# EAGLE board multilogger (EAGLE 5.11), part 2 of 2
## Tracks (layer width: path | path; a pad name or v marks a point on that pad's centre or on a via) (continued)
N$23 (continued)
  Top 0.254: R38.1 51.38,156.84 52.42,156.84 52.99,156.2 53.8,156.2 54.63,156.23 IC1.10
N$24  (via drill 0.3)
  Top 0.254: v61.94,32.68 61.94,31.26 R16.2
  Bottom 0.254: v61.94,32.68 61.4,32.72 60.99,32.72 59.91,34.31 59.91,34.72 X1.8
N$25
  Top 0.254: R18.2 4.64,67.02 4.64,62.76 5.66,61.74 IN3_PLUS_CON.MP | R18.2
N$26
  Top 0.254: R19.2 10.74,56.46 10.74,56.25 10.13,55.65 5.86,55.65 5.86,56.46 IN3_MINUS_CON.MP | R19.2
N$27
  Top 0.254: IC1.4 63.91,152.5 C20.1
N$28
  Top 0.254: IC1.5 63.91,153.76 C20.2
N$29
  Top 0.254: R20.2 10.74,50.36 5.86,50.36 5.86,51.38 IN4_PLUS_CON.MP
N$30
  Top 0.254: R21.2 10.74,45.28 9.52,45.28 8.5,46.3 5.86,46.3 IN4_MINUS_CON.MP
N$31
  Top 0.254: C21.1 58.9,144.24 58.9,148.71 60.12,149.93 60.93,149.93 IC1.2
N$32
  Top 0.254: IC1.6 62.17,155.03 63.57,156.43 63.57,157.23 C22.1
N$33
  Top 0.254: R24.2 50.36,162.32 53,162.32 53,163.14 53.14,163.28 55.17,163.28 55.24,161.92 56.05,161.11 57.58,159.78 57.68,158.67 57.68,153.18 55.85,151.35 54.83,151.35 IC1.14
N$34
  Top 0.254: R25.2 54.22,162.32 54.88,160.65 55.65,160.09 56.76,158.46 56.76,153.99 55.85,152.57 54.83,152.57 IC1.13
N$35
  Top 0.254: R24.1 50.36,164.36 50.36,168.22 RS232-TX-CON.MP
N$36
  Top 0.254: R25.1 54.02,164.36 54.02,168.22 RS232-RX-CON.MP
N$37
  Top 0.254: R36.1 54.63,154.4 54.63,155.01 IC1.11
N$38
  Top 0.254: X2.2 12.79,24.54 13.79,23.54 13.8,23.54 R28.2
N$39
  Top 0.254: R37.1 51.38,151.96 52.39,151.96 52.39,152.16 53.82,153.59 54.63,153.59 IC1.12
N$40  (via drill 0.3)
  Top 0.254: v53.27,157.25 54.63,157.25 54.63,157.45 IC1.9 | R39.1 v52.8,142.61
  Bottom 0.254: v52.8,142.61 52.8,156.79 53,157.04 v53.27,157.25
N$41
  Top 0.254: X2.3 12.77,23.74 13.38,23.13 13.38,20.15 R29.2
N$43
  Top 0.254: C25.1 17.55,25.5 IC2.3 20.29,25.37 20.29,24.35 IC2.4 20.29,24.15 20.29,23.13 IC2.5
N$44
  Top 0.254: R40.2 61.74,162.32 62.15,161.92 62.15,158.34 62.35,157.85 62.35,156.97 61.54,156.15 61.13,156.43 IC1.7
N$45
  Top 0.254: R41.2 57.88,162.32 60.93,159.28 60.93,157.65 IC1.8
N$46  (via drill 0.3)
  Top 0.254: v59.62,65.17 59.3,65.6 58.08,65.6 IC7.33 | v48.33,55.03 47.31,54.02 47.31,52.6 BUTTON4.MP
  Bottom 0.254: v59.62,65.17 58.29,63.98 58.29,61.94 58.49,61.94 59.1,61.33 59.1,59.51 51.17,59.51 50.16,58.49 50.16,56.86 v48.33,55.03
N$47  (via drill 0.3)
  Top 0.254: v57.84,61.18 57.55,61.26 56.86,61.77 55.9,62.91 55.9,64.38 56.51,64.99 57.88,64.99 IC7.32 | v43.66,60.73 43.45,60.52 43.45,58.9 43.25,58.69 43.25,57.88 42.49,56.84 42.49,55.8 38.58,54.38 38.58,50.16 35.58,45.38 24.81,45.38 24.55,47.52 v22.52,49.55 | v16.02,49.14 14.6,49.14 14.39,48.94 4.03,48.94 4.03,72.92 10.94,77.03 10.94,78.81 BUTTON3.MP
  Bottom 0.254: v57.84,61.18 57.47,60.73 v43.66,60.73 | v22.52,49.55 22.12,49.14 v16.02,49.14
N$48
  Top 0.254: R40.1 61.74,164.36 61.74,168.22 RS232-RTS-CON.MP
N$49
  Top 0.254: R41.1 RS232-CTS-CON.MP
N$50
  Top 0.254: R43.1 78.2,146.47 77.79,146.88 77.79,148.3 75.36,150.74 75.15,150.74 75.15,150.54 IC8.4
N$51  (via drill 0.3)
  Top 0.254: v49.14,69.26 49.14,67.71 49.95,67.02 50.72,63.98 52.32,61.74 52.32,60.32 IC7.17 | v39.6,69.54 39.67,69.37 39.36,69.2 36.82,69.2 36.63,69.73 36.42,70.52 36.38,72.29 34.42,75.2 31.41,75.39 31.4,77.44 30.7,84.8 BUTTON2.MP
  Bottom 0.254: v49.14,69.26 48.74,69.47 v39.6,69.54
N$52  (via drill 0.3)
  Top 0.254: v42.64,58.08 42.64,58.9 43.05,59.3 43.05,61.33 48.33,61.33 49.38,62.01 49.89,62.21 50.97,62.27 51.78,61.33 51.78,60.32 IC7.16 | v33.9,54.02 33.09,53.21 33.09,52.6 BUTTON1.MP
  Bottom 0.254: v42.64,58.08 42.44,58.29 38.17,58.29 37.56,57.68 37.56,56.5 36.82,56.5 v33.9,54.02
N$53
  Top 0.254: IC2.6 17.55,21.68 R28.1
N$54
  Top 0.254: IC2.7 18.82,20.41 R29.1
N$55
  Top 0.254: R42.1 70.68,146.47 71.09,146.88 71.09,150.34 IC8.1
N$56
  Top 0.254: R44.1 74.34,146.47 74.34,149.93 73.93,150.34 IC8.3
N$57
  Top 0.254: IC2.11 32.8,21.68 R30.2
N$58
  Top 0.254: R45.2 51.38,93.24 51.38,97.1 OLED.5
N$59
  Top 0.254: IC2.10 30.89,20.41 R31.2
N$60  (via drill 0.3)
  Top 0.254: 61.74,37.76 63.16,37.76 63.16,37.15 63.98,36.34 63.98,35.12 R17.2 | v61.74,36.75 61.74,37.76 | 61.74,37.76 R53.1
  Bottom 0.254: v61.74,36.75 61.74,34.92 X1.7
N$61
  Top 0.254: R47.2 44.06,93.24 44.27,93.44 44.27,94.86 46.3,96.89 46.3,97.1 OLED.9
N$62
  Top 0.254: R46.2 55.24,93.24 55.03,93.44 55.03,95.47 54.02,96.49 54.02,97.1 OLED.3
N$63  (via drill 0.3)
  Top 0.254: v66.62,36.75 66.62,37.76 R52.1
  Bottom 0.254: v66.62,36.75 66.62,34.92 X1.5
N$64  (via drill 0.3)
  Top 0.254: v60.12,32.48 60.12,32.68 58.08,34.72 58.08,36.34 56.66,37.76 R51.1
  Bottom 0.254: v60.12,32.48 60.52,32.07 72.71,32.07 74.14,33.5 74.14,34.72 X1.2
N$65  (via drill 0.3)
  Top 0.254: v65.6,38.78 65.6,37.97 64.38,37.97 R50.1
  Bottom 0.254: v65.6,38.78 66.82,37.56 70.89,37.56 71.09,37.36 73.93,37.36 76.37,34.92 76.57,34.92 X1.1
N$66  (via drill 0.3)
  Top 0.254: v58.69,35.12 59.1,35.53 59.1,37.36 | 59.1,37.36 59.1,37.76 R48.2 59.1,37.36 | 59.1,37.36 57.68,38.84 55.65,38.84 55.44,38.58 55.44,37.97 54.22,37.97 R5.1
  Bottom 0.254: v58.69,35.12 57.88,34.31 X1.DETECT
N$67  (via drill 0.3)
  Top 0.254: 63.37,62.96 v63.37,64.59 | v64.99,65.4 65.13,66.36 65.19,66.62 R49.2 | v71.09,29.23 71.49,29.64 71.49,36.95 70.68,37.76 70.68,44.27 71.7,45.28 71.7,53.61 70.26,55.34 69.28,56.32 v68.67,56.32 | v63.57,61.74 63.37,61.94 63.37,62.96 | 63.37,62.96 R7.1
  Bottom 0.254: v63.37,64.59 64.18,65.4 v64.99,65.4 | v71.09,29.23 64.79,22.93 57.07,22.93 56.66,22.52 X1.WRITE_PROT | v68.67,56.32 v63.57,61.74
N$68
  Top 0.254: IC9.1 66.21,94.25 62.76,94.25 62.76,94.66 R54.1
N$69
  Top 0.254: IC9.2 66.21,93.64 64.99,93.64 62.76,91.41 62.76,91 R55.1
N$70
  Top 0.254: IC10.36 69.06,127.37 68.45,127.98 66.82,127.98 66.21,128.59 61.74,128.59 61.74,139.16 AD9540_CP_OUT.MP
N$71  (via drill 0.3)
  Top 0.254: v65.6,125.14 66.54,125.75 68.02,125.75 68.12,125.67 68.62,125.67 IC10.39
  Bottom 0.254: v65.6,125.14 60.46,130.09 55.99,130.09 54.22,131.73 54.22,135.3 56.46,135.3 AD9540_REFIN.MP
N$73
  Top 0.254: IC7.56 53.76,77.04 52.58,81.12 52.39,81.78 Y2.4 52.16,83.92 51.58,84.5 48.72,84.5 C13.1
N$74
  Top 0.254: IC7.55 54.26,77.02 54.29,80.3 55.24,81.91 Y2.1 | Y2.1 55.66,82.01 | C12.1 56.7,83.55 56.24,83.09 55.24,82.11 Y2.1
N$75
  Top 0.254: IC7.43 66.21,70.54 68.43,76.26 70.68,80.44 70.68,81.33 Y1.2 75.19,81.53 C15.1
N$76
  Top 0.254: IC7.42 68.49,70.04 Y1.1 74.89,72.03 C14.1
N$77  (via drill 0.3)
  Top 0.254: v67.63,125.14 68.45,125.14 IC10.40
  Bottom 0.254: v67.63,125.14 66.61,123.92 !AD9540_REFIN.MP
N$78  (via drill 0.3)
  Top 0.254: v73.32,130.63 73.32,130.14 72.59,129.53 72.59,127.45 IC10.29
  Bottom 0.254: v73.32,130.63 73.32,139.16 AD9540_CLK1.MP
N$79  (via drill 0.3)
  Top 0.254: v73.21,129.22 73.12,129 73.12,127.37 IC10.28
  Bottom 0.254: v73.21,129.22 73.78,130.02 76.98,133.47 76.98,139.16 !AD9540_CLK1.MP
N$80  (via drill 0.3)
  Top 0.254: v66.21,124.53 66.21,124.12 68.45,124.12 IC10.42
  Bottom 0.254: v66.21,124.53 61.94,124.53 58.69,127.78 56.66,127.78 AD9540_CLK2.MP
N$81  (via drill 0.3)
  Top 0.254: v66.82,125.14 67.18,124.53 68.03,124.53 68.17,124.63 68.45,124.68 IC10.41
  Bottom 0.254: v66.82,125.14 60.52,131.44 56.66,131.44 !AD9540_CLK2.MP
N$82
  Top 0.254: IC10.9 73.09,120.49 73.09,119.47 73.13,118.99 73.13,118.79 73.48,117.81 73.73,117.21 74.34,116.61 74.34,108.68 AD9540_IO_RESET.MP
N$83
  Top 0.254: AD9540_RESET.MP 78.2,110.71 74.75,114.17 74.75,116.81 74.34,117.21 73.89,118.39 73.58,119.68 73.58,120.49 IC10.10
N$84  (via drill 0.3)
  Top 0.254: v76.02,120.42 75.36,121.08 IC10.13
  Bottom 0.254: v76.02,120.42 82.06,114.37 82.06,108.68 AD9540_SD0.MP
N$85  (via drill 0.3)
  Top 0.15: v76.98,120.47 75.76,121.69 75.15,121.69 IC10.14
  Bottom 0.15: v76.98,120.47 84.5,112.95 84.5,112.74 AD9540_SDIO.MP
  Bottom 0.254: AD9540_SDIO.MP 84.55,112.74
N$86  (via drill 0.3)
  Top 0.254: v77.36,121.18 75.7,122.17 IC10.15
  Bottom 0.254: v77.36,121.18 81.76,116.53 84.5,116.4 AD9540_SCLK.MP
N$87  (via drill 0.3)
  Top 0.254: v76.66,122.43 75.97,122.7 75.15,122.7 IC10.16
  Bottom 0.254: v76.66,122.43 82.02,121.71 84.5,120.06 !AD9540_CS.MP
N$88  (via drill 0.3)
  Top 0.254: v67.44,121.32 67.63,121.69 68.45,121.69 IC10.47
  Bottom 0.254: v67.44,121.32 65.81,120.06 60.73,120.06 59.1,118.43 59.1,112.54 56.66,112.54 AD9540_DAC_RSET.MP
N$89  (via drill 0.3, 0.3 pad 0.25)
  Top 0.254: IC10.46 68.08,122.23 67.6,122.21 66.71,121.83 v65.82,122.84 | v55.34,118.33 55.34,117.57 AD9540_DRV_RSET.MP
  Bottom 0.254: v65.82,122.84 58.9,122.84 55.21,121.32 55.21,118.46 v55.34,118.33
N$90  (via drill 0.3)
  Top 0.254: v66.77,122.74 68.4,122.67 IC10.45
  Bottom 0.254: v66.77,122.74 66.21,122.09 60.73,122.09 58.69,120.06 56.66,120.06 AD9540_CP_RSET.MP
N$91
  Top 0.254: IC10.23 75.15,126.16 75.6,126.18 76.12,126.55 79.22,129.2 79.22,137.53 84.5,142.82 AD9540_S2.MP
N$92
  Top 0.254: IC10.22 75.94,125.67 79.62,127.72 79.62,134.08 84.5,138.96 84.5,139.16 AD9540_S1.MP
N$93
  Top 0.254: IC10.21 75.15,125.14 76.22,125.14 77.54,125.62 78.4,126.23 80.22,127.42 80.28,130.76 AD9540_S0.MP
N$94
  Top 0.254: IC10.20 76.36,124.68 77.44,125 80.3,126.33 81.5,127.98 84.3,129.89 AD9540_IO_UPDATE.MP
N$95
  Top 0.254: IC10.19 76.57,124.17 78.47,124.92 80.36,125.43 82.26,127.78 84.5,127.78 AD9540_SYNC_IN.MP
N$96  (via drill 0.3)
  Top 0.254: v77.39,123.79 77.39,123.72 75.15,123.72 IC10.18
  Bottom 0.254: v77.39,123.79 AD9540_SYNC_OUT.MP
N$97  (via drill 0.3)
  Top 0.254: v71.49,118.43 71.49,119.25 71.6,119.42 71.6,120.44 IC10.6
  Bottom 0.254: v71.49,118.43 66.82,113.76 66.82,108.68 !AD9540_IOUT.MP
N$98
  Top 0.254: IC10.5 71.09,120.47 71.09,119.65 69.67,118.23 69.67,111.73 70.48,110.92 70.48,108.68 AD9540_IOUT.MP
N$99
  Top 0.254: IC10.32 71.09,127.37 71.09,129.61 69.87,130.83 69.87,136.52 69.26,137.13 69.26,139.16 !AD9540_OUT0.MP
N$100
  Top 0.254: IC10.33 70.61,127.45 70.61,129.28 69.46,130.42 69.46,135.1 65.6,138.96 65.6,139.16 AD9540_OUT0.MP
N$101
  Top 0.254: D9.A 17.24,8.35 9V-BAT-PLUS-CON.MP
N$102
  Bottom 0.254: POWER-PLUS-CON.MP D10.A
N$104
  Top 0.254: IC5.4 60.32,106.44 60.32,103.8 60.12,103.6 C36.2
N$105
  Top 0.254: C30.2 IC3.1 45.18,22.32 38.83,22.32 38.83,13.43 33.75,13.43 D9.C
  Bottom 0.254: D10.C 45.18,22.32 IC3.1
N$106
  Top 0.254: IC3.3 40.1,29.23 38.98,29.23 38.98,32.89 C31.2 39.05,34.51 42.23,34.51 42.64,32.8 C37.2 43.86,32.77 IC6.8
N$107
  Top 0.254: IC11.7 80.03,52.6 82.06,52.6 82.06,52.39 84.09,50.36 84.5,50.36 CODEC_LRCOUT.MP
N$108
  Top 0.254: C38.2 28.99,34.99 IC13.4 29.73,36.14 47.11,36.14 47.92,35.33 47.92,34.51 47.49,34.08 IC6.6
N$109
  Top 0.254: IC6.4 51.78,34.72 48.86,37.83 48.86,38.84 47.72,39.8 R56.1
N$110
  Top 0.254: R58.1 66.54,18.19 VR1.3 65.82,17.95 R57.2
N$111
  Top 0.254: IC11.2 79.83,49.22 79.11,49.22 76.98,46.7 76.98,38.98 CODEC_CLKOUT.MP
N$112
  Top 0.254: IC11.3 80.03,49.75 80.44,49.75 80.64,49.55 80.64,38.98 CODEC_BCLK.MP
N$113
  Top 0.254: IC11.4 80.03,50.56 80.23,50.56 81.25,49.55 81.25,42.23 84.5,38.98 CODEC_DIN.MP
N$114
  Top 0.254: IC11.6 80.03,51.78 81.05,51.78 82.06,50.77 82.06,48.94 CODEC_DOUT.MP
N$115
  Top 0.254: IC11.5 80.03,51.17 80.49,51.17 81.65,49.75 81.65,45.69 84.5,42.84 84.5,42.64 CODEC_LRCIN.MP
N$116
  Top 0.254: IC11.9 80.03,53.82 84.5,53.82 84.5,54.02 CODEC_LHPOUT.MP
N$117
  Top 0.254: IC11.10 80.03,54.43 81.25,54.43 84.5,57.68 84.5,57.88 CODEC_RHPOUT.MP
N$118
  Top 0.254: CODEC_XTI_MCLK.MP 73.12,44.67 72.31,45.48 72.31,49.14 73.34,50.42 73.53,50.56 73.93,50.56 IC11.25
N$119
  Top 0.254: IC11.26 74.14,49.75 75.56,49.75 75.94,49.14 75.97,41.83 73.12,38.98 CODEC_XTO.MP
N$120  (via drill 0.3)
  Top 0.254: v72.92,50.97 72.92,51.17 73.93,51.17 IC11.24
  Bottom 0.254: v72.92,50.97 72.92,49.75 71.09,47.92 70.57,47.92 69.46,46.5 CODEC_SCLK.MP
N$121  (via drill 0.3)
  Top 0.254: v72.54,51.78 73.93,51.78 IC11.23
  Bottom 0.254: v72.54,51.78 71.49,50.36 69.46,50.36 CODEC_SDIN.MP
N$122  (via drill 0.3)
  Top 0.254: v72.92,52.6 73.93,52.6 IC11.22
  Bottom 0.254: v72.92,52.6 71.49,54.02 69.46,54.02 CODEC_MODE.MP
N$123
  Top 0.254: IC11.21 73.93,53.21 72.1,53.21 72.1,53.82 70.3,56.38 69.67,57.68 69.46,57.88 !CODEC_CS.MP
N$124
  Top 0.254: IC11.12 80.03,55.85 82.06,55.85 82.06,59.1 84.5,61.54 CODEC_LOUT.MP
N$125
  Top 0.254: IC11.13 80.03,56.46 81.25,56.46 81.65,56.86 81.65,62.55 84.5,65.4 CODEC_ROUT.MP
N$126
  Top 0.254: IC11.20 73.93,53.82 72.71,53.82 71.63,55.53 70.81,59.35 CODEC_LLINEIN.MP
N$127  (via drill 0.3)
  Top 0.254: v72.92,54.65 73.53,54.43 73.93,54.43 IC11.19
  Bottom 0.254: v72.92,54.65 72.92,62.96 71.9,62.96 69.46,65.4 CODEC_RLINEIN.MP
N$128
  Top 0.254: IC11.18 73.93,55.03 73.53,55.03 73.4,55.17 72.1,56.41 72.1,62.35 73.12,63.37 CODEC_MICIN.MP
N$129
  Top 0.254: IC11.17 74,55.72 73.53,55.72 72.51,56.86 72.51,61.13 76.78,65.4 CODEC_MICBIAS.MP
N$130
  Top 0.254: IC11.16 74.14,56.36 76.93,56.41 76.93,60.14 80.64,63.77 80.64,65.4 CODEC_VMID.MP
OLED_RESET  (via drill 0.3)
  Top 0.254: v46.09,86.94 46.09,87.55 44.27,89.38 44.27,91 44.06,91.2 R47.1 | v51.99,77.18 v51.99,80.82 | v55.92,72.92 56.86,72.51 57.88,72.51 IC7.47
  Bottom 0.254: v46.09,86.94 51.99,81.05 v51.99,80.82 | v51.99,77.18 54.98,72.92 v55.92,72.92
OLED_RX
  Top 0.254: IC7.49 57.88,73.53 57.27,73.53 56.81,73.78 56.81,74.31 57.27,74.97 57.65,75.7 57.68,78 57.68,82.26 59.16,83.69 59.16,85.52 57.68,86.94 57.68,89.58 56.05,91.2 55.44,91.2 R46.1
OLED_TX  (via drill 0.3)
  Top 0.254: v57.02,76.68 56.76,75.08 56.25,74.34 56.25,73.73 57.02,73.04 57.83,73.04 IC7.48 | v55.77,77.74 56.46,78.4 v56.46,80.03 | v52.19,89.58 51.58,90.19 51.58,91.2 R45.1
  Bottom 0.254: v57.02,76.68 v55.77,77.74 | v56.46,80.03 53,83.48 53,89.58 v52.19,89.58
PWM1  (via drill 0.3)
  Top 0.254: v48.33,62.15 47.52,62.96 42.64,62.96 IC7.98 | v65.81,65.4 v69.06,68.65 | v92.42,71.49 93.44,72.51 93.44,135.3 96.89,138.75 96.89,139.36 CON2.1
  Bottom 0.254: v48.33,62.15 49.82,63.7 57.07,63.57 59.51,66.01 65.39,66.01 v65.81,65.4 | v69.06,68.65 71.9,71.49 v92.42,71.49
PWM2  (via drill 0.3)
  Top 0.254: v43.66,55.65 44.62,56.46 44.89,58.13 45.02,58.53 45.28,59.3 45.28,60.12 IC7.3 | v42.23,54.43 41.62,53.82 v41.62,37.57 | v100.15,72.71 100.15,75.36 99.13,76.37 99.13,87.34 99.84,88.44 99.84,91.69 99.94,91.81 99.94,92.22 100.75,93.03 100.75,130.83 97.1,134.49 CON2.2
  Bottom 0.254: v43.66,55.65 42.44,54.43 v42.23,54.43 | v41.62,37.57 42.03,37.36 55.03,37.36 57.88,40.2 74.34,40.2 78.2,44.06 85.72,44.06 93.44,51.78 99.22,51.78 100.55,50.39 100.96,50.39 101.57,51.12 101.57,68.36 101.16,68.86 100.75,69.27 100.75,72.71 v100.15,72.71
PWM_KILL  (via drill 0.3)
  Top 0.254: v43.86,56.66 43.86,59.71 44.27,60.12 IC7.1 | v63.98,47.72 v65.19,47.72 | v92.42,66.62 93.85,68.04 93.85,125.75 96.89,128.8 96.89,129.41 CON3.1
  Bottom 0.254: v43.86,56.66 46.7,53.82 48.13,53.82 50.36,51.58 56.05,51.58 59.91,47.72 v63.98,47.72 | v65.19,47.72 67.84,45.08 69.87,45.08 82.64,56.61 82.77,56.74 82.77,58.58 83.85,59.72 84.74,59.72 87.22,60.97 v92.42,66.62
RS232_CTS  (via drill 0.3)
  Top 0.15: v42.23,40.2 42.23,49.55 47.31,54.63 47.31,60.12 IC7.7 | v51.58,139.36 52.8,139.36 R39.2
  Bottom 0.15: v42.23,40.2 35.33,33.29 26.08,33.29 25.18,34.19 25.18,36.35 24.1,37.43 4.69,37.48 1.73,38.47 1.8,126.56 35.12,126.56 47.92,139.36 v51.58,139.36
RS232_RTS  (via drill 0.3)
  Top 0.254: v60.29,63.54 59.71,64.03 58.08,64.03 IC7.30 | v74.95,67.02 78.61,70.68 85.72,70.68 v85.72,85.71 | v100.96,86.94 101.16,87.14 101.16,147.29 v100.96,147.49 | v101.59,171.27 101.57,171.32 101.36,171.52 47.72,171.47 47.72,160.09 49.35,158.46 49.35,157.04 R38.2
  Bottom 0.254: v60.29,63.54 60.93,63.98 66.41,63.98 67.84,65.21 67.84,67.02 v74.95,67.02 | v85.72,85.71 87.14,86.94 v100.96,86.94 | v100.96,147.49 100.96,170.05 101.36,170.45 v101.59,171.27
RS232_RX  (via drill 0.3)
  Top 0.15: v40.41,66.82 40.81,67.23 40.81,67.43 42.44,67.43 IC7.89 | v33.84,62.15 27.2,69.87 26.18,69.87 26.18,71.29 25.77,71.7 25.77,75.15 25.16,75.76 v25.16,127.17 | v48.53,150.54 49.14,151.15 49.14,151.76 R37.2
  Bottom 0.15: v40.41,66.82 35.73,62.15 v33.84,62.15 | v25.16,127.17 v48.53,150.54
RS232_TX  (via drill 0.3)
  Top 0.15: 47.72,60.12 IC7.8
  Top 0.254: v91.2,62.55 91.41,62.76 v91.41,82.67 | v101.36,82.47 101.57,82.67 101.57,170.25 100.75,171.06 64.18,171.06 v64.18,167.41 | v50.77,155.62 49.35,155.62 49.35,154.4 R36.2 | 47.72,60.12 47.72,58.13 49.56,56.29 50.32,56.29 v50.55,56.25
  Bottom 0.254: v50.55,56.25 51.17,55.44 52.8,55.44 59.91,48.33 64.51,48.33 64.55,48.29 64.59,47.92 64.59,46.7 65.6,46.7 67.63,44.67 71.09,44.67 73.73,47.31 79.83,47.31 82.06,49.55 82.06,54.55 86,56.77 v91.2,62.55 | v91.41,82.67 91.61,82.47 v101.36,82.47 | v64.18,167.41 54.63,157.85 52.81,157.85 v50.77,155.62
RS485-A
  Top 0.254: R22.1 74.54,160.5 74.75,160.7 74.75,165.78 75.76,166.79 CON12.2
RS485-B
  Top 0.254: R23.1 70.68,160.5 70.68,167 CON12.1
RS485_RX  (via drill 0.3)
  Top 0.254: v46.7,57.27 46.7,60.12 IC7.6 | v54.92,52.38 55.65,51.78 v55.65,50.97 | v86.94,54.43 86.94,94.23 92.02,99.31 v92.02,133.67 | v70.89,143.43 70.68,143.63 70.68,144.44 R42.2
  Bottom 0.254: v46.7,57.27 47.72,56.25 47.72,54.43 52.88,54.43 v54.92,52.38 | v55.65,50.97 60.32,46.3 65.4,46.3 67.63,44.06 71.09,44.06 73.93,46.91 80.03,46.91 83.08,49.95 83.08,51.58 85.49,52.41 v86.94,54.43 | v92.02,133.67 85.11,140.58 83.28,140.58 80.44,143.43 v70.89,143.43
RS485_TX  (via drill 0.3)
  Top 0.254: v47.92,78.81 48.13,78.61 48.13,77.06 47.78,76.65 47.78,75.97 IC7.68 | v52.39,88.77 54.22,90.59 54.22,92.02 54.43,92.17 57.47,92.17 57.47,95.27 64.38,102.18 v64.38,106.6 | v76.42,127.81 78.4,130.22 78.4,144.24 78.2,144.44 R43.2
  Bottom 0.254: v47.92,78.81 49.35,80.23 51.51,80.17 51.85,79.83 52.19,79.83 52.6,80.23 52.6,88.77 v52.39,88.77 | v64.38,106.6 64.79,107 68.74,107 68.74,110.01 75.15,115.18 75.15,127.46 v76.42,127.81
RS485_TX_EN  (via drill 0.3)
  Top 0.254: v51.58,71.7 51.78,71.49 51.78,67.23 51.58,66.83 51.58,65.6 51.38,65.4 51.38,64.38 51.89,64.38 54.76,61.51 IC7.22 | v64.18,82.47 63.98,82.67 63.98,87.55 68.45,92.02 68.45,103.6 63.16,108.88 63.16,118.23 60.32,121.08 60.32,139.77 63.16,142.61 74.34,142.61 74.34,144.44 R44.2
  Bottom 0.254: v51.58,71.7 51.58,76.4 51.38,76.6 51.38,77.86 52.38,77.86 53.61,76.24 57.38,75.8 58.08,77.39 63.98,77.39 64.79,78.2 64.79,82.47 v64.18,82.47
SDCARD_CHIPSELECT  (via drill 0.3)
  Top 0.254: v65.82,42.26 64.79,41.42 64.79,40.2 64.38,39.8 R50.2 | v67.42,43.27 67.02,43.86 67.02,53.66 67.23,54.38 67.23,64.18 66.82,64.59 v66.82,65.19 | v49.14,71.49 46.7,73.93 45.78,73.93 45.28,74.75 45.28,75.76 IC7.73
  Bottom 0.254: v65.82,42.26 66.96,42.96 v67.42,43.27 | v66.82,65.19 65.11,67.23 59.9,67.23 56.86,70.07 50.37,70.07 v49.14,71.49
SDCARD_CLOCK  (via drill 0.3)
  Top 0.254: v66.62,54.7 66.62,39.8 R52.2 | v59.3,62.15 58.9,62.55 58.08,62.55 IC7.27
  Bottom 0.254: v66.62,54.7 v59.3,62.15
SDCARD_DETECT  (via drill 0.3)
  Top 0.254: v60.24,64.51 59.12,64.51 58.87,64.53 58.06,64.53 IC7.31 | v66.62,55.65 66.01,55.16 66.03,49.12 66.21,48.13 66.21,43.66 62.96,40.41 62.96,39.19 62.6,38.83 60.78,38.83 59.91,39.59 59.3,39.59 R48.1
  Bottom 0.254: v60.24,64.51 59.86,64.42 59.39,63.51 60.28,61.92 v66.62,55.65
SDCARD_MISO  (via drill 0.3)
  Top 0.254: v55.52,74.31 55.75,74.97 IC7.52 | v60.73,67.84 60.93,67.63 60.93,63.16 60.73,62.96 60.73,62.35 v61.13,61.94 | v64.38,58.69 64.23,58.39 64.23,54.78 65.6,49.02 65.81,47.92 65.78,44.34 61.72,40.28 61.74,39.8 R53.2
  Bottom 0.254: v55.52,74.31 56.25,74.14 60.32,74.14 60.32,73.67 60.93,73.06 61.94,72.51 61.94,67.84 v60.73,67.84 | v64.38,58.69 v61.13,61.94
SDCARD_MOSI  (via drill 0.3)
  Top 0.254: v45.69,80.44 45.5,79.75 44.88,78.81 44.88,76.98 44.74,76.73 44.74,76.3 IC7.74 | v50.77,80.84 51.17,80.44 v51.17,79.5 | v87.55,82.67 87.95,82.26 v87.95,54.41 | v57.07,41.01 56.66,40.61 56.66,39.8 R51.2
  Bottom 0.254: v45.69,80.44 46.09,80.84 v50.77,80.84 | v51.17,79.5 51.38,79.42 57.47,79.42 62.35,84.3 85.92,84.3 v87.55,82.67 | v87.95,54.41 86.94,53.21 86.94,48.69 83.09,48.69 79.42,45.08 72.71,45.08 68.65,41.01 v57.07,41.01
SDCARD_WRITE_PROTECT
  Top 0.254: IC7.28 58.06,63.04 59.89,63.04 60.22,62.55 60.22,61.94 60.83,61.33 61.54,61.33 61.69,61.51 62.29,62.35 62.29,63.77 62.31,64.56 62.63,65.17 63.37,65.72 63.37,66.62 R49.1
SPI_CLOCK  (via drill 0.3)
  Top 0.254: v48.33,74.54 48.33,75.76 IC7.67 | v50.36,79.62 50.16,79.83 50.16,82.45 49.55,83.06 49.55,83.08 49.14,83.48 47.72,83.48 47.72,85.52 49.55,87.34 v49.55,89.99 | v87.2,103.47 87,104.06 87,106.74 87.34,107.46 87.34,117.42 89.38,119.45 SPI-CLOCK-CON.MP
  Bottom 0.254: v48.33,74.54 48.33,77.13 49.8,77.13 50.13,77.12 50.36,78.81 v50.36,79.62 | v49.55,89.99 53.61,94.05 77.59,94.05 v87.2,103.47 | CON4.1 96.89,119.45 89.58,119.45 SPI-CLOCK-CON.MP
SPI_MISO  (via drill 0.3)
  Top 0.15: 48.33,60.12 IC7.9
  Top 0.254: v50.83,57.3 49.55,57.68 49.35,57.88 48.8,57.88 48.33,58.35 48.33,60.12 | v70.21,48.81 71.09,48.13 v71.09,47.31 | v82.25,66.86 86.47,70.06 86.53,107.26 86.94,107.66 86.94,121.89 89.38,124.33 SPI-MISO-CON.MP
  Bottom 0.254: v50.83,57.3 52.19,56.25 52.6,56.25 59.91,48.94 v70.21,48.81 | v71.09,47.31 82.06,58.29 v82.25,66.86 | CON3.2 96.89,124.53 89.58,124.53 SPI-MISO-CON.MP
SPI_MOSI  (via drill 0.3)
  Top 0.254: v67.63,69.26 67.06,69.21 60.97,69.21 60.12,68.47 60.12,66.01 58.08,66.01 IC7.34 | v100.75,76.98 100.75,85.92 v100.96,86.12
  Bottom 0.254: v67.63,69.26 70.48,72.1 98.72,72.1 100.75,74.52 v100.75,76.98 | v100.96,86.12 101.57,86.42 101.57,114.37 97.1,114.37 CON4.2 96.89,114.37 89.58,114.37 SPI-MOSI-CON.MP
SWD_CK  (via drill 0.3)
  Top 0.254: v54.83,58.29 54.83,58.9 54.22,59.51 54.22,60.12 IC7.21 | v58.29,53.41 57.88,53 MINIPROG2.4
  Bottom 0.254: v54.83,58.29 56.66,56.46 56.66,54.22 57.47,54.22 v58.29,53.41
SWD_IO  (via drill 0.3)
  Top 0.254: v53.82,58.29 53.82,60.12 IC7.20 | v56.86,53.54 56.86,51.99 56.66,51.78 MINIPROG2.2
  Bottom 0.254: v53.82,58.29 56.25,55.85 56.25,53.82 56.46,53.82 v56.86,53.54
SWD_SWO  (via drill 0.3)
  Top 0.254: v55.85,58.29 55.85,58.9 55.24,59.51 55.24,60.12 IC7.23 | v59.1,53.41 59.1,51.78 MINIPROG2.6
  Bottom 0.254: v55.85,58.29 57.07,56.75 57.07,54.63 58.26,54.63 v59.1,53.41
USB-PIN  (via drill 0.3)
  Top 0.254: v42.23,39.19 45.79,43.76 48.94,48.69 48.94,52.19 52.39,55.65 52.39,58.9 52.8,59.3 52.8,60.12 IC7.18 | v31.06,23.74 30.45,23.13 29.64,23.13 IC2.12
  Bottom 0.254: v42.23,39.19 31.06,28.01 v31.06,23.74
VDAC  (via drill 0.3 pad 0.25)
  Top 0.254: IC7.99 41.9,62.54 v41.18,62.58 | v38.77,60.36 38.77,60.61 38.39,60.93 36.23,61.24 35.66,61.69 35.15,62.71 33.94,67.02 35.34,68.36 35.21,69.88 35.27,70.07 35.78,70.83 35.78,72.17 34.26,74.52 34.07,74.71 33.69,74.71 30.64,74.83 29.18,74.83 28.73,73.56 26.38,73.69 26.19,75.6 25.75,77.18 26.13,125.83 29.18,130.02 33.94,166.59 39.66,172.24 102.65,172.18 v102.33,141.89
  Bottom 0.254: v38.77,60.36 v41.18,62.58 | v102.33,141.89 92.87,141.95 93.12,147.1 CON1.1
(copper drawn outside any net)
  shapes: Bottom circle x5

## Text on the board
Top: MultiLogger V 0.1 | http://www.frank-buss.de/MultiLogger/index.html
